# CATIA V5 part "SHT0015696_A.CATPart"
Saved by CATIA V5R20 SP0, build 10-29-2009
Part number: SHT0015696
Revision: A
Definition: 后地脚钣金
Property "单位": "PC"
Bounding box of the stored display mesh (mm): x -124.809 to 124.192, y -64.487 to -34.048, z -369.992 to -355.318
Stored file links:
  C:\TCIC_V5_tmp\catuii\SHT0015696_A.CATPart
  E:\Gao Bingchuan\PDM\CATIA 零件自定义属性_外部_20180629\CATIA 零件自定义属性_外部_20180704.txt
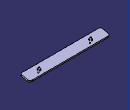
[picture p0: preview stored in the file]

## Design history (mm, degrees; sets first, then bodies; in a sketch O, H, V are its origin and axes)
Set1
  Line1: type Normal, RefPoint {point type Center, Curve edge [face of Solid1 | face of Solid1]}, RefSkin face of Solid1, Start -5, End 10
  Line2: type Normal, RefPoint {point type Center, Curve edge [face of Solid1 | face of Solid1]}, RefSkin face of Solid1, Start -5, End 10
Body1 (main body)
  Solid1 "实体.29": solid without history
